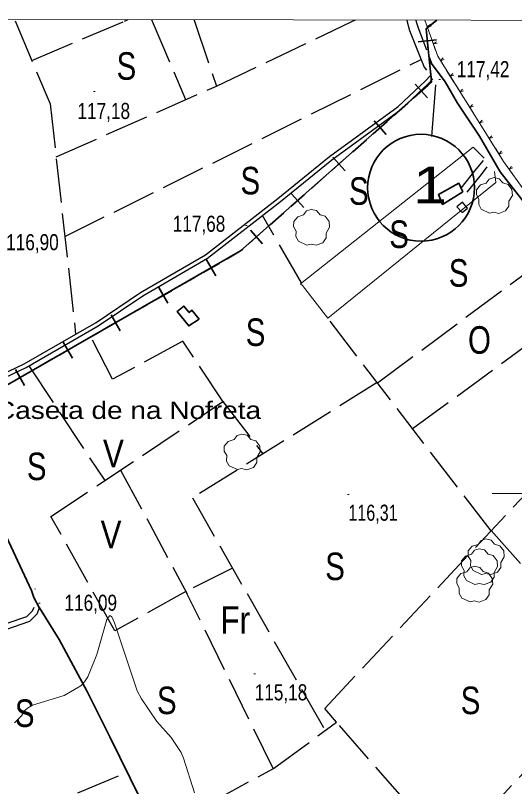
# Model space of a CAD drawing. Extents: x 483840 to 488445, y 4386047 to 4389027.
# Drawn here: x 485215.3 to 485487.2, y 4388340.3 to 4388760.3 of the extents above; entities that cross this region are included whole.
import ezdxf
from ezdxf.enums import TextEntityAlignment as Align

# ---------------------------------------------------------------- set-up
doc = ezdxf.new("R2010")
doc.units = 0
doc.header["$LTSCALE"] = 4
doc.linetypes.add('LONG_DASHED', pattern=[7.5, 6, -1.5])
doc.linetypes.add('MEDIUM_DASHED', pattern=[4.5, 3, -1.5])
for name, color, linetype, lineweight in [('1', 7, 'Continuous', 13), ('21', 7, 'Continuous', 25), ('24', 7, 'Continuous', 13), ('25', 7, 'LONG_DASHED', 25), ('29', 7, 'Continuous', 13), ('34', 7, 'Continuous', 35), ('36', 7, 'Continuous', 25), ('38', 7, 'Continuous', 25), ('47', 7, 'Continuous', 35), ('51', 7, 'Continuous', 13), ('6', 7, 'Continuous', 35), ('7', 7, 'Continuous', 13), ('9', 7, 'Continuous', 13)]:
    doc.layers.add(name, color=color, linetype=linetype, lineweight=lineweight)
doc.layers.add('31', color=7, linetype='Continuous')
doc.layers.add('5', color=7, linetype='Continuous')

msp = doc.modelspace()

# ---------------------------------------------------------------- linework, layer by layer
at = {"layer": '1'}
msp.add_line((485475, 4388500), (485525, 4388500), dxfattribs=at)
msp.add_lwpolyline([(484110.5, 4388760.3), (487685.8, 4388753.5), (487681.9, 4386441.2), (484105.5, 4386448.1)], close=True, dxfattribs=at)
at = {"layer": '21'}
msp.add_lwpolyline([(485461.57, 4388655.38), (485458.79, 4388658.52), (485455.8, 4388655.97), (485458.65, 4388653.05)], close=True, dxfattribs=at)
at = {"layer": '24'}
for p, q in [((485438.36, 4388757.77), (485440.86, 4388750.7)), ((485441.69, 4388748.34), (485444.19, 4388741.27)), ((485450.15, 4388730.35), (485454.13, 4388724)), ((485455.46, 4388721.88), (485459.44, 4388715.52)), ((485460.77, 4388713.4), (485464.75, 4388707.04)), ((485466.07, 4388704.92), (485470.05, 4388698.57)), ((485471.38, 4388696.45), (485475.36, 4388690.09)), ((485476.69, 4388687.97), (485480.67, 4388681.62)), ((485482.07, 4388679.55), (485486.44, 4388673.45))]:
    msp.add_line(p, q, dxfattribs=at)
for points in [[(485438.36, 4388757.77), (485445.31, 4388738.09), (485481.19, 4388680.78), (485497.87, 4388657.48), (485522.1, 4388627.89), (485556.4, 4388595.45), (485658.37, 4388675.43), (485610.22, 4388730.53), (485644.61, 4388757.38)], [(485441.31, 4388755.41), (485439.61, 4388754.23), (485441.67, 4388754.4)], [(485444.64, 4388745.98), (485442.94, 4388744.8), (485445, 4388744.97)], [(485445.02, 4388738.91), (485445.31, 4388738.09), (485448.83, 4388732.47)], [(485448.25, 4388737.17), (485446.84, 4388735.65), (485448.81, 4388736.26)], [(485453.55, 4388728.69), (485452.14, 4388727.17), (485454.12, 4388727.79)], [(485458.86, 4388720.22), (485457.45, 4388718.7), (485459.43, 4388719.31)], [(485464.17, 4388711.74), (485462.76, 4388710.22), (485464.73, 4388710.83)], [(485469.47, 4388703.27), (485468.06, 4388701.75), (485470.04, 4388702.36)], [(485474.78, 4388694.79), (485473.37, 4388693.27), (485475.35, 4388693.88)], [(485480.09, 4388686.31), (485478.68, 4388684.79), (485480.65, 4388685.41)], [(485485.57, 4388678.1), (485484.25, 4388676.5), (485486.19, 4388677.23)]]:
    msp.add_lwpolyline(points, dxfattribs=at)
at = {"layer": '25'}
for p, q in [((485224.3, 4388735.75), (485274.68, 4388757.19)), ((485274.67, 4388757.19), (485276.77, 4388758.08)), ((485289.48, 4388758.06), (485289.86, 4388757.16)), ((485289.86, 4388757.16), (485308.03, 4388714.43)), ((485312.54, 4388758.01), (485312.84, 4388757.12)), ((485398.61, 4388756.95), (485400.5, 4388757.85)), ((485242.26, 4388639.87), (485436.3, 4388736.29)), ((485237.45, 4388683.26), (485324.79, 4388721.84)), ((485371.16, 4388614.66), (485349.84, 4388651.28)), ((485412.5, 4388560.17), (485507.83, 4388630.91)), ((485431.63, 4388535.24), (485530.42, 4388607.73)), ((485474.34, 4388479.58), (485385.46, 4388595.39)), ((485222.56, 4388569.4), (485264.04, 4388506.97)), ((485272.64, 4388512.72), (485308.86, 4388445.29)), ((485333.6, 4388459.21), (485308.21, 4388446.59)), ((485138.58, 4388290.73), (485276.3, 4388348.15))]:
    msp.add_line(p, q, dxfattribs=at)
for points in [[(485215.21, 4388757.31), (485234.26, 4388712.09), (485248.14, 4388586.71)], [(485312.84, 4388757.12), (485324.79, 4388721.84), (485398.62, 4388756.95)], [(485328.92, 4388549.28), (485306.49, 4388582.89), (485268.19, 4388562.12), (485254.87, 4388588.06)], [(485294.89, 4388316.98), (485355.86, 4388350.2), (485390.25, 4388375.38), (485383.86, 4388382.88), (485564.51, 4388575.95)], [(485412.4, 4388560.3), (485311.73, 4388497.53), (485384.02, 4388370.82)], [(485355.68, 4388350.1), (485308.21, 4388446.59), (485269.47, 4388425.22), (485234.71, 4388487.35), (485328.37, 4388549.99), (485350.09, 4388521.45)], [(485474.44, 4388479.69), (485543.08, 4388402.79), (485605.61, 4388468.78)], [(485546.85, 4388406.77), (485459.36, 4388312.64), (485447.06, 4388310.22)], [(485338.32, 4388231.98), (485447.06, 4388310.22), (485390.25, 4388375.38)]]:
    msp.add_lwpolyline(points, dxfattribs=at)
at = {"layer": '29'}
for points in [[(485473.59, 4388652.59), (485469.05, 4388654.71), (485467.64, 4388657.25), (485467.74, 4388660.23), (485466.37, 4388662.64), (485466.41, 4388665.39), (485468.57, 4388667.99), (485471.76, 4388668.99), (485473.41, 4388671.18), (485475.98, 4388672.01), (485478.84, 4388671.36), (485480.79, 4388669.09), (485483.6, 4388668.27), (485485.73, 4388665.42), (485485.97, 4388662.29), (485484.09, 4388659.14), (485484.09, 4388656.46), (485482.27, 4388653.85), (485478.65, 4388652.51), (485475.88, 4388653.14)], [(485374.08, 4388635.25), (485369.54, 4388637.37), (485368.13, 4388639.91), (485368.23, 4388642.89), (485366.86, 4388645.3), (485366.9, 4388648.05), (485369.06, 4388650.65), (485372.25, 4388651.65), (485373.9, 4388653.84), (485376.47, 4388654.67), (485379.33, 4388654.02), (485381.28, 4388651.75), (485384.09, 4388650.93), (485386.22, 4388648.08), (485386.46, 4388644.95), (485384.58, 4388641.8), (485384.58, 4388639.12), (485382.76, 4388636.51), (485379.14, 4388635.17), (485376.37, 4388635.8)], [(485336.25, 4388512.91), (485331.71, 4388515.03), (485330.3, 4388517.57), (485330.4, 4388520.55), (485329.03, 4388522.96), (485329.07, 4388525.71), (485331.23, 4388528.31), (485334.42, 4388529.31), (485336.07, 4388531.5), (485338.64, 4388532.33), (485341.5, 4388531.68), (485343.45, 4388529.41), (485346.26, 4388528.59), (485348.39, 4388525.74), (485348.63, 4388522.61), (485346.75, 4388519.46), (485346.75, 4388516.78), (485344.93, 4388514.17), (485341.31, 4388512.83), (485338.54, 4388513.46)], [(485469.11, 4388455.82), (485464.57, 4388457.94), (485463.16, 4388460.48), (485463.26, 4388463.46), (485461.89, 4388465.87), (485461.93, 4388468.62), (485464.09, 4388471.22), (485467.28, 4388472.22), (485468.93, 4388474.41), (485471.5, 4388475.24), (485474.36, 4388474.59), (485476.31, 4388472.32), (485479.12, 4388471.5), (485481.25, 4388468.65), (485481.49, 4388465.52), (485479.61, 4388462.37), (485479.61, 4388459.69), (485477.79, 4388457.08), (485474.17, 4388455.74), (485471.4, 4388456.37)], [(485465.52, 4388450.41), (485460.98, 4388452.53), (485459.57, 4388455.07), (485459.67, 4388458.05), (485458.3, 4388460.46), (485458.34, 4388463.21), (485460.5, 4388465.81), (485463.69, 4388466.81), (485465.34, 4388469), (485467.91, 4388469.83), (485470.77, 4388469.18), (485472.72, 4388466.91), (485475.53, 4388466.09), (485477.66, 4388463.24), (485477.9, 4388460.11), (485476.02, 4388456.96), (485476.02, 4388454.28), (485474.2, 4388451.67), (485470.58, 4388450.33), (485467.81, 4388450.96)], [(485462.91, 4388440.88), (485458.37, 4388443), (485456.96, 4388445.54), (485457.06, 4388448.52), (485455.69, 4388450.93), (485455.73, 4388453.68), (485457.89, 4388456.28), (485461.08, 4388457.28), (485462.73, 4388459.47), (485465.3, 4388460.3), (485468.16, 4388459.65), (485470.11, 4388457.38), (485472.92, 4388456.56), (485475.05, 4388453.71), (485475.29, 4388450.58), (485473.41, 4388447.43), (485473.41, 4388444.75), (485471.59, 4388442.14), (485467.97, 4388440.8), (485465.2, 4388441.43)]]:
    msp.add_lwpolyline(points, close=True, dxfattribs=at)
at = {"layer": '34'}
for p, q in [((485441.63, 4388755.16), (485444.8, 4388757.76)), ((485440.19, 4388741.47), (485439.16, 4388751.41)), ((485434.71, 4388745.92), (485444.65, 4388746.95)), ((485441.74, 4388726.56), (485440.71, 4388736.5)), ((485432.69, 4388715.76), (485440.18, 4388722.39)), ((485433.12, 4388722.82), (485439.75, 4388715.33)), ((485421.46, 4388705.83), (485428.95, 4388712.46)), ((485410.23, 4388695.89), (485417.72, 4388702.52)), ((485410.66, 4388702.95), (485417.28, 4388695.46)), ((485399, 4388685.96), (485406.49, 4388692.59)), ((485387.76, 4388676.02), (485395.25, 4388682.65)), ((485388.2, 4388683.08), (485394.82, 4388675.59)), ((485376.54, 4388666.09), (485384.03, 4388672.72)), ((485365.3, 4388656.15), (485372.79, 4388662.78)), ((485365.73, 4388663.21), (485372.36, 4388655.72)), ((485354.07, 4388646.22), (485361.56, 4388652.85)), ((485342.84, 4388636.28), (485350.33, 4388642.91)), ((485343.27, 4388643.34), (485349.9, 4388635.85)), ((485317.59, 4388620.29), (485326.26, 4388625.27)), ((485319.44, 4388627.12), (485324.41, 4388618.44)), ((485304.59, 4388612.84), (485313.26, 4388617.81)), ((485293.42, 4388612.2), (485298.4, 4388603.52)), ((485291.58, 4388605.37), (485300.25, 4388610.35)), ((485278.57, 4388597.92), (485287.25, 4388602.89)), ((485265.56, 4388590.45), (485274.23, 4388595.43)), ((485267.41, 4388597.28), (485272.38, 4388588.6)), ((485252.56, 4388583), (485261.23, 4388587.97)), ((485241.39, 4388582.36), (485246.37, 4388573.68)), ((485239.54, 4388575.53), (485248.22, 4388580.51)), ((485226.54, 4388568.08), (485235.22, 4388573.05)), ((485213.53, 4388560.61), (485222.2, 4388565.59)), ((485215.38, 4388567.44), (485220.35, 4388558.76))]:
    msp.add_line(p, q, dxfattribs=at)
for points in [[(484742, 4388368), (485071, 4388510), (485202, 4388554), (485338, 4388632), (485442, 4388724), (485439, 4388753), (485444.8, 4388757.76)], [(485330.6, 4388627.76), (485338, 4388632), (485339.1, 4388632.98)]]:
    msp.add_lwpolyline(points, dxfattribs=at)
at = {"layer": '36'}
for p, q in [((485428.42, 4388757.79), (485428.66, 4388756.89)), ((485433.39, 4388757.78), (485433.66, 4388756.88))]:
    msp.add_line(p, q, dxfattribs=at)
for points in [[(485428.65, 4388756.89), (485429.91, 4388752.09), (485437.97, 4388732.15), (485439.26, 4388730.4)], [(485433.65, 4388756.88), (485434.63, 4388753.6), (485439.14, 4388741.64)]]:
    msp.add_lwpolyline(points, dxfattribs=at)
at = {"layer": '38'}
msp.add_line((485226.23, 4388447.63), (485226.02, 4388448.03), dxfattribs=at)
for points in [[(485177.05, 4388545.26), (485178.07, 4388546.88), (485182.09, 4388549.16), (485187.49, 4388552.58), (485221.18, 4388568.6), (485260.38, 4388591.25), (485284.66, 4388607.57), (485320.02, 4388628.07), (485359.66, 4388658.93), (485387.64, 4388681.69), (485425.25, 4388709.1), (485437.25, 4388720.39), (485439.94, 4388722.85), (485442.73, 4388725.7)], [(485177.32, 4388548.97), (485180.97, 4388551.04), (485186.43, 4388554.5), (485220.16, 4388570.53), (485259.22, 4388593.11), (485283.5, 4388609.42), (485318.8, 4388629.88), (485358.29, 4388660.64), (485386.3, 4388683.42), (485423.85, 4388710.78), (485435.76, 4388721.99), (485438.46, 4388724.47), (485441.33, 4388727.59)], [(485472.11, 4388677.84), (485469.03, 4388673.73), (485461.25, 4388664.04)], [(485030.66, 4388348.53), (485062.6, 4388363.45), (485091.99, 4388375.2), (485128.12, 4388388.53), (485167.92, 4388409.53), (485201.51, 4388423.01), (485223.17, 4388430.4), (485227.22, 4388434.38), (485228.44, 4388437.61)], [(485073.67, 4388370.72), (485080.11, 4388373.42), (485126.9, 4388391.22), (485166.68, 4388412.21), (485200.48, 4388425.77), (485221.58, 4388432.97), (485224.69, 4388436.03), (485225.46, 4388438.06)]]:
    msp.add_lwpolyline(points, dxfattribs=at)
at = {"layer": '38', "linetype": 'MEDIUM_DASHED'}
msp.add_lwpolyline([(485469.98, 4388681.37), (485465.38, 4388675.63), (485457.66, 4388666.02)], dxfattribs=at)
at = {"layer": '47'}
for points in [[(485458.93, 4388664.15), (485456.83, 4388668.87), (485445.66, 4388662.7), (485447.94, 4388657.35)], [(485315.4, 4388594.9), (485311.49, 4388599.7), (485309.98, 4388598.48), (485307.12, 4388602.01), (485303.42, 4388599.02), (485309.76, 4388591.17)]]:
    msp.add_lwpolyline(points, close=True, dxfattribs=at)
at = {"layer": '51'}
msp.add_lwpolyline([(485470.53, 4388682.55), (485464.67, 4388688.61), (485370.58, 4388614.2), (485371.63, 4388613.15), (485385.46, 4388595.39), (485477.01, 4388669.36), (485476.25, 4388675.21)], dxfattribs=at)
at = {"layer": '6', "lineweight": 25}
msp.add_line((485442.05, 4388694.37), (485444.29, 4388722.47), dxfattribs=at)
at = {"layer": '6'}
for points in [[(485440.7, 4388737.5), (485441.99, 4388734.08), (485449.36, 4388724.07), (485456.08, 4388712.46), (485468.1, 4388694.6), (485479.36, 4388675.04), (485491.14, 4388660.05), (485511.34, 4388633.52), (485528.76, 4388616.39), (485543.57, 4388599.11), (485561.47, 4388584.67), (485581.34, 4388566.46), (485601.43, 4388546.21), (485625.33, 4388523.43), (485648.4, 4388503.95), (485672.73, 4388482.48), (485688.17, 4388467.01), (485707.06, 4388435), (485712.35, 4388418.05), (485721.25, 4388387.26), (485731.78, 4388354.89)], [(485224.04, 4388447.11), (485207.78, 4388482.2), (485189.48, 4388517.58), (485178.95, 4388536.92), (485175.21, 4388541.77), (485174.76, 4388545.72), (485175.43, 4388546.79)], [(485228.46, 4388437.56), (485225.43, 4388443.22), (485224.04, 4388447.11)], [(485228.44, 4388437.61), (485239.13, 4388420.45), (485254.49, 4388392.02), (485266.8, 4388367.49), (485283.36, 4388333.76), (485295.91, 4388308.62), (485304.83, 4388288.39), (485316.35, 4388267.98), (485320.79, 4388259.19)]]:
    msp.add_lwpolyline(points, dxfattribs=at)
msp.add_circle((485436.23, 4388666.46), 29.1, dxfattribs=at)
at = {"layer": '7'}
for p, q in [((485445.88, 4388725.49), (485446.88, 4388725.49)), ((485257.83, 4388718.88), (485258.83, 4388718.88)), ((485340.62, 4388645.88), (485341.62, 4388645.88)), ((485396.14, 4388499.47), (485397.14, 4388499.47)), ((485227.83, 4388440.16), (485228.83, 4388440.16)), ((485345.14, 4388401.64), (485346.14, 4388401.64))]:
    msp.add_line(p, q, dxfattribs=at)
at = {"layer": '9'}
msp.add_lwpolyline([(485312.87, 4388336.86), (485306.95, 4388355.83), (485305.55, 4388358.92), (485300.12, 4388367.09), (485292.4, 4388375.67), (485284.01, 4388388.01), (485281.55, 4388392.44), (485269.32, 4388429.52), (485267.84, 4388432.73), (485267.03, 4388433.22), (485266.84, 4388433.25), (485266.66, 4388433.23), (485266.17, 4388432.81), (485265.75, 4388432.15), (485265.51, 4388431.84), (485265.03, 4388431.39), (485259.75, 4388412.31), (485254.79, 4388400.03), (485252.96, 4388397.44), (485250.91, 4388395.19), (485241.86, 4388389.98), (485224.65, 4388384.68), (485221.84, 4388383.04), (485220.54, 4388381.77), (485218.64, 4388378.8), (485214.76, 4388375.08)], dxfattribs=at)

# ---------------------------------------------------------------- texts
at = {"layer": '31'}
for s, width, p in [('S', 0.8, (485275.79, 4388725.26)), ('S', 0.8, (485343.26, 4388662.83)), ('S', 0.8, (485402.38, 4388657.17)), ('S', 0.8, (485424.27, 4388633.64)), ('S', 0.8, (485456.7, 4388612.55)), ('S', 0.8, (485346.12, 4388580.28)), ('O', 0.8, (485468.04, 4388576.05)), ('V', 0.85, (485268.71, 4388514.24)), ('S', 0.8, (485226.92, 4388507.21)), ('V', 0.85, (485267.42, 4388470.11)), ('S', 0.8, (485389.41, 4388452.76)), ('Fr', 0.85, (485335.08, 4388423.56)), ('S', 0.8, (485297.78, 4388379.76)), ('S', 0.8, (485463.18, 4388379.76)), ('S', 0.8, (485220.4, 4388372.79))]:
    msp.add_text(s, height=15, dxfattribs=dict(at, width=width)).set_placement(p, align=Align.CENTER)
at = {"layer": '5', "width": 1.2}
msp.add_text('Caseta de na Nofreta', height=9.5, dxfattribs=at).set_placement((485349.13, 4388540.53), align=Align.RIGHT)
at = {"layer": '6', "width": 1.25}
msp.add_text('1', height=20, dxfattribs=at).set_placement((485441.14, 4388658), align=Align.CENTER)
at = {"layer": '7'}
for s, width, p in [('117,42', 0.8, (485455.71, 4388726.66)), ('117,18', 0.8, (485249.14, 4388703.9)), ('117,68', 0.8, (485301, 4388642.47)), ('116,90', 0.8, (485210.29, 4388632.42)), ('116,31', 0.75, (485396.64, 4388485.1)), ('116,09', 0.8, (485242.06, 4388436.06)), ('115,18', 0.8, (485345.64, 4388387.27))]:
    msp.add_text(s, height=8.75, dxfattribs=dict(at, width=width)).set_placement(p)

doc.saveas('drawing.dxf')
